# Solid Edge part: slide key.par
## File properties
Title: Slide Key
Author: Abhinav Rai
Template: Normal.par
Last saved by: Cadcim
Revision: 8
Application: Solid Edge
Density: 0.0000078 kg/mm^3
Accuracy: 0.01
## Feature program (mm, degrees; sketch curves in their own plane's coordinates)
sketch for "unnamed Protrusion 1" plane through (0, 0, 0) normal (0, -1, 0) x-axis (1, 0, 0)
  line (-30.0365, -12.1146) -> (28.6883, -12.1146)
  line (28.6883, -12.1146) -> (28.6883, -17.6629)
  line (1.9812, -17.6629) -> (28.6883, -17.6629)
  line (1.9812, -13.3979) -> (1.9812, -17.6629)
  line (-1.9812, -13.3979) -> (1.9812, -13.3979)
  line (-1.9812, -17.6629) -> (-1.9812, -13.3979)
  line (-30.0365, -17.6629) -> (-1.9812, -17.6629)
  line (-30.0365, -17.6629) -> (-30.0365, -12.1146)
extrude "unnamed Protrusion 1" add finite 4.7244 along +normal
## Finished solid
Body 1: solid body, 10 faces, 24 edges, 16 vertices.
  Faces by surface: plane 10
  Edges by curve: line 24
Bounding box of the edges (mm): 58.725 x 4.724 x 5.548, from (-30.0365, -4.7244, -17.6629) to (28.6883, 0, -12.1146).
Planar faces by outward normal: +x 2, +y 1, +z 1, -x 2, -y 1, -z 3
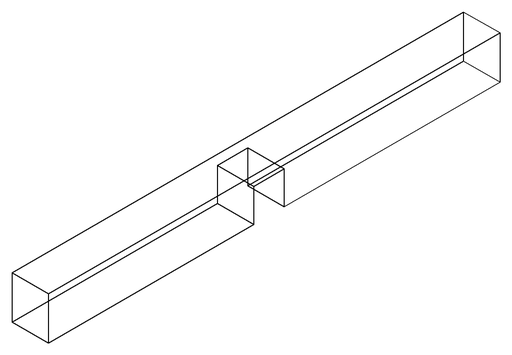
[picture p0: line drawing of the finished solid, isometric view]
